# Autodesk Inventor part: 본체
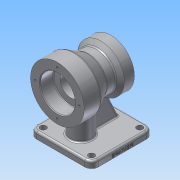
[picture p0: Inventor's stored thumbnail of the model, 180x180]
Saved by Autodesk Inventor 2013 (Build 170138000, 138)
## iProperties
Created: 2019-01
Part Number: 본체
Material: 알루미늄 6061
Document SubType Name: Modeling
Designer: Administrator
Density: 2.71 g/cm^3
Mass: 903.951 g
Surface Area: 601.923 cm^2
Volume: 333.561 cm^3
Author: Administrator
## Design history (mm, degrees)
sketch "스케치1"
  geometry: L1 (-40, 0)-(-40, 40); L2 (-40, 40)-(-15, 40); L3 (-15, 40)-(5.785, 28); L4 (5.785, 28)-(19.126, 28); L5 (19.126, 28)-(25, 35); L6 (25, 35)-(40, 35); L7 (40, 35)-(40, 0); L8 (40, 0)-(-40, 0); 2 further points
  constraints: 16 end point, 3 parallel, 2 perpendicular, 1 coincident, 1 midpoint, 1 vertical
  dimensions: "d0" = 80 diameter of L2 L8; "d2" = 56 diameter of L4 L8; "d3" = 70 diameter of L6 L8; "d4" = 25 distance of L1.end L2.end; "d5" = 15 distance of L5.end L6.end; "d6" = 80 distance of L7.end L1.start; "d8" = 130 deg angle of L4 L5; "d9" = 150 deg angle of L3 L4
revolve "회전1" sketch "스케치1" stored, may be unused: angle "d10" = 90 deg
node "작업 평면1"
sketch "스케치2"
  geometry: L1 (35, 46)-(-57, 46); L2 (-57, 46)-(-57, -46); L3 (-57, -46)-(35, -46); L4 (35, -46)-(35, 46); L5 (35, 46)-(-57, -46); L6 (-57, 46)-(35, -46); L7 (40, 40)-(40, -40) reference; 2 further points
  constraints: 12 end point, 2 parallel, 1 horizontal, 1 horizontal alignment, 1 midpoint, 1 perpendicular
  dimensions: "d12" = 92 distance of L2.end L3.end; "d14" = 92 distance of L1.end L2.end; "d80" = 5 distance between parallel lines of L4 L7
extrude "돌출1" join sketch "스케치2" distance "d15" = 10; taper "d16" = 0 deg
sketch "스케치3"
  geometry: L1 (57, 46)-(-35, 46) reference; L2 (-35, 46)-(-35, -46) reference; C1 r 16 at (-5, 0); 1 further point
  constraints: 1 centre point
  dimensions: "d17" = 32 diameter of C1; "d18" = 30 distance from line of L2 C1.centre; "d19" = 46 distance from line of C1.centre L1
extrude "돌출2" join sketch "스케치3" stored distance "d20" = 10; taper "d21" = 0 deg
sketch "스케치4"
  geometry: L1 (-40, 40)-(-15, 40) reference; L2 (-15, 40)-(5.785, 28) reference; L3 (5.785, 28)-(19.126, 28) reference; L4 (19.126, 28)-(25, 35) reference; L5 (25, 35)-(40, 35) reference; L6 (40, 35)-(40, -35) reference; L7 (40, -35)-(25, -35) reference; L8 (25, -35)-(19.126, -28) reference; L9 (19.126, -28)-(11, -28) reference; L10 (11, -28)-(11, -70) reference; L11 (11, -70)-(57, -70) reference; L12 (57, -70)-(57, -80) reference; L13 (57, -80)-(-35, -80) reference; L14 (-35, -80)-(-35, -70) reference; L15 (-35, -70)-(-21, -70) reference; L16 (-21, -70)-(-21, -40) reference; L17 (-21, -40)-(-40, -40) reference; L18 (-40, -40)-(-40, 40) reference; L19 (47, -70)-(18.199, -8.236); 1 further point
  constraints: 2 end point, 1 point on line
  dimensions: "d24" = 10 distance of L11.end L19.start; "d25" = 25 deg angle of L12 L19
feature "리브1" sketch "스케치4" dims "d26" = 1, "d27" = 10, "d28" = 0, "d29" = 0, "d30" = 1, "d31" = 1
sketch "스케치5"
  geometry: L1 (-21, -40)-(-40, -40) reference; L2 (-40, -40)-(-40, 40) reference; L3 (-40, 40)-(-15, 40) reference; L4 (-15, 40)-(5.785, 28) reference; L5 (5.785, 28)-(19.126, 28) reference; L6 (25, 35)-(40, 35) reference; L7 (40, 35)-(40, -35) reference; L8 (40, -35)-(30.679, -35) reference; L9 (19.126, 28)-(25, 35) reference; L10 (30.679, -35)-(47, -70) reference; L11 (47, -70)-(57, -70) reference; L12 (57, -70)-(57, -80) reference; L13 (57, -80)-(-35, -80) reference; L14 (-35, -80)-(-35, -70) reference; L15 (-35, -70)-(-21, -70) reference; L16 (-21, -70)-(-21, -40) reference; L17 (-40, 26)-(-20, 26); L18 (-20, 26)-(-20, 16); L19 (-20, 16)-(25, 16); L20 (25, 16)-(25, 20); L21 (25, 20)-(40, 20); L22 (40, 20)-(40, 0); L23 (40, 0)-(-40, 0); L24 (-40, 0)-(-40, 26); 1 further point
  constraints: 16 end point, 3 perpendicular, 2 midpoint, 2 parallel, 2 point on line, 1 collinear
  dimensions: "d32" = 52 diameter of L17 L23; "d34" = 32 diameter of L19 L23; "d35" = 40 diameter of L21 L23; "d36" = 20 distance of L17.start L17.end; "d37" = 15 distance of L20.end L21.end
revolve "회전2" sketch "스케치5" stored, may be unused: angle "d38" = 90 deg
sketch "스케치6" dims "d39" = 66
  geometry: C1 r 26 at (0, 0) reference; C2 r 40 at (0, 0) reference; 2 further points
  constraints: 2 vertical alignment, 1 coincident, 2 other
hole "구멍1" sketch "스케치6" at (0, 33) diameter "d40" = 3.242; stored, may be unused: countersink angle "d44" = 90 deg, drill point angle "d46" = 118 deg; dims "d41" = 9, "d42" = 4, "d43" = 2, "d45" = 11
sketch "스케치7" dims "d50" = 55
  geometry: C1 r 20 at (0, 0) reference; C2 r 35 at (0, 0) reference; 2 further points
  constraints: 2 vertical alignment, 1 coincident, 2 other
hole "구멍2" sketch "스케치7" at (0, 27.5) diameter "d51" = 3.242; stored, may be unused: countersink angle "d55" = 90 deg, drill point angle "d57" = 118 deg; dims "d52" = 9, "d53" = 4, "d54" = 2, "d56" = 11
fillet "모깎기1" dims "d61" = 10
sketch "스케치8"
  geometry: C1 r 4.5 at (-25, 36); A1 r 10 centre (-25, 36) between (-25, 46) and (-35, 36) reference; 1 further point
  constraints: 1 centre point, 1 coincident
  dimensions: "d62" = 9 diameter of C1
extrude "돌출3" cut sketch "스케치8" stored distance "d63" = 10; taper "d64" = 0 deg
sketch "스케치9"
  geometry: C1 r 4.5 at (47, 36); A1 r 10 centre (47, 36) between (57, 36) and (47, 46) reference; 1 further point
  constraints: 1 centre point, 1 coincident
  dimensions: "d65" = 9 diameter of C1
extrude "돌출4" cut sketch "스케치9" distance "d66" = 10; taper "d67" = 0 deg
sketch "스케치10"
  geometry: C1 r 4.5 at (-25, -36); A1 r 10 centre (-25, -36) between (-35, -36) and (-25, -46) reference; 1 further point
  constraints: 1 centre point, 1 coincident
  dimensions: "d68" = 9 diameter of C1
extrude "돌출5" cut sketch "스케치10" distance "d69" = 10; taper "d70" = 0 deg
sketch "스케치11"
  geometry: C1 r 4.5 at (47, -36); A1 r 10 centre (47, -36) between (47, -46) and (57, -36) reference; 1 further point
  constraints: 1 centre point, 1 coincident
  dimensions: "d71" = 9 diameter of C1
extrude "돌출6" cut sketch "스케치11" distance "d72" = 10; taper "d73" = 0 deg
fillet "모깎기2" dims "d74" = 1
fillet "모깎기3" dims "d75" = 0.6
fillet "모깎기4" dims "d76" = 3
fillet "모깎기5" dims "d77" = 3
fillet "모깎기7" dims "d79" = 3
fillet "모깎기8" dims "d81" = 2
fillet "모깎기9" dims "d82" = 2
chamfer "모따기1" distance "d83" = 1; stored, may be unused: second distance "d84" = 2, angle "d85" = 45 deg
node "작업 평면2"
sketch "스케치12"
  geometry: L1 (-10, 7)-(-10, 0) reference; L2 (82, 0)-(72, 0) reference; 2 further points
  constraints: 1 other
  dimensions: "d87" = 46 distance from line of point (36, 4) L1; "d88" = 4 distance from line of L2 point (36, 4)
feature "엠보싱1" sketch "스케치12" dims "d89" = 0.5, "d90" = 0
node "솔리드1"
pattern_circular "원형 패턴1" dims angle "d48" = 360 deg
pattern_circular "원형 패턴2" dims angle "d59" = 360 deg
node "절단 모서리 투영1"
node "절단 모서리 투영2"
other parameters: "d86" = 92
